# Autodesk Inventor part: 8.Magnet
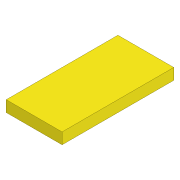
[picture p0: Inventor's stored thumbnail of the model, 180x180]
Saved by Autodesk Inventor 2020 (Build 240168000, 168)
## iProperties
Created: 2022-02
Part Number: 8.Magnet
Material: Steel
Document SubType Name: Modeling
Designer: marti
Density: 7.85 g/cm^3
Appearance: Plate
Mass: 3.14 g
Surface Area: 5.2 cm^2
Volume: 0.4 cm^3
Author: marti
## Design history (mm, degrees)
sketch "Sketch1"
  geometry: L1 (5, 10)-(-5, 10); L2 (-5, 10)-(-5, -10); L3 (-5, -10)-(5, -10); L4 (5, -10)-(5, 10); L5 (5, 10)-(-5, -10); L6 (-5, 10)-(5, -10); 1 further point
  constraints: 12 end point, 2 midpoint, 2 parallel, 1 horizontal, 1 perpendicular
  dimensions: "d0" = 10 distance of L3.end L2.end; "d1" = 20 distance of L2.end L1.end
extrude "Extrusion1" new body sketch "Sketch1" distance "d2" = 2; taper "d3" = 0 deg
body "Solid1"
